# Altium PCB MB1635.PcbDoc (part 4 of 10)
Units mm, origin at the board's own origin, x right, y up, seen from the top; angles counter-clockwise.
Board outline 127 x 97 mm, 6 copper layers (Top Layer, Signal Layer 1, Signal Layer 2, Signal Layer 3, Signal Layer 4, Bottom Layer), stack 1.557 mm thick; 593 components, 478 nets, 2435 pads, 1743 vias.
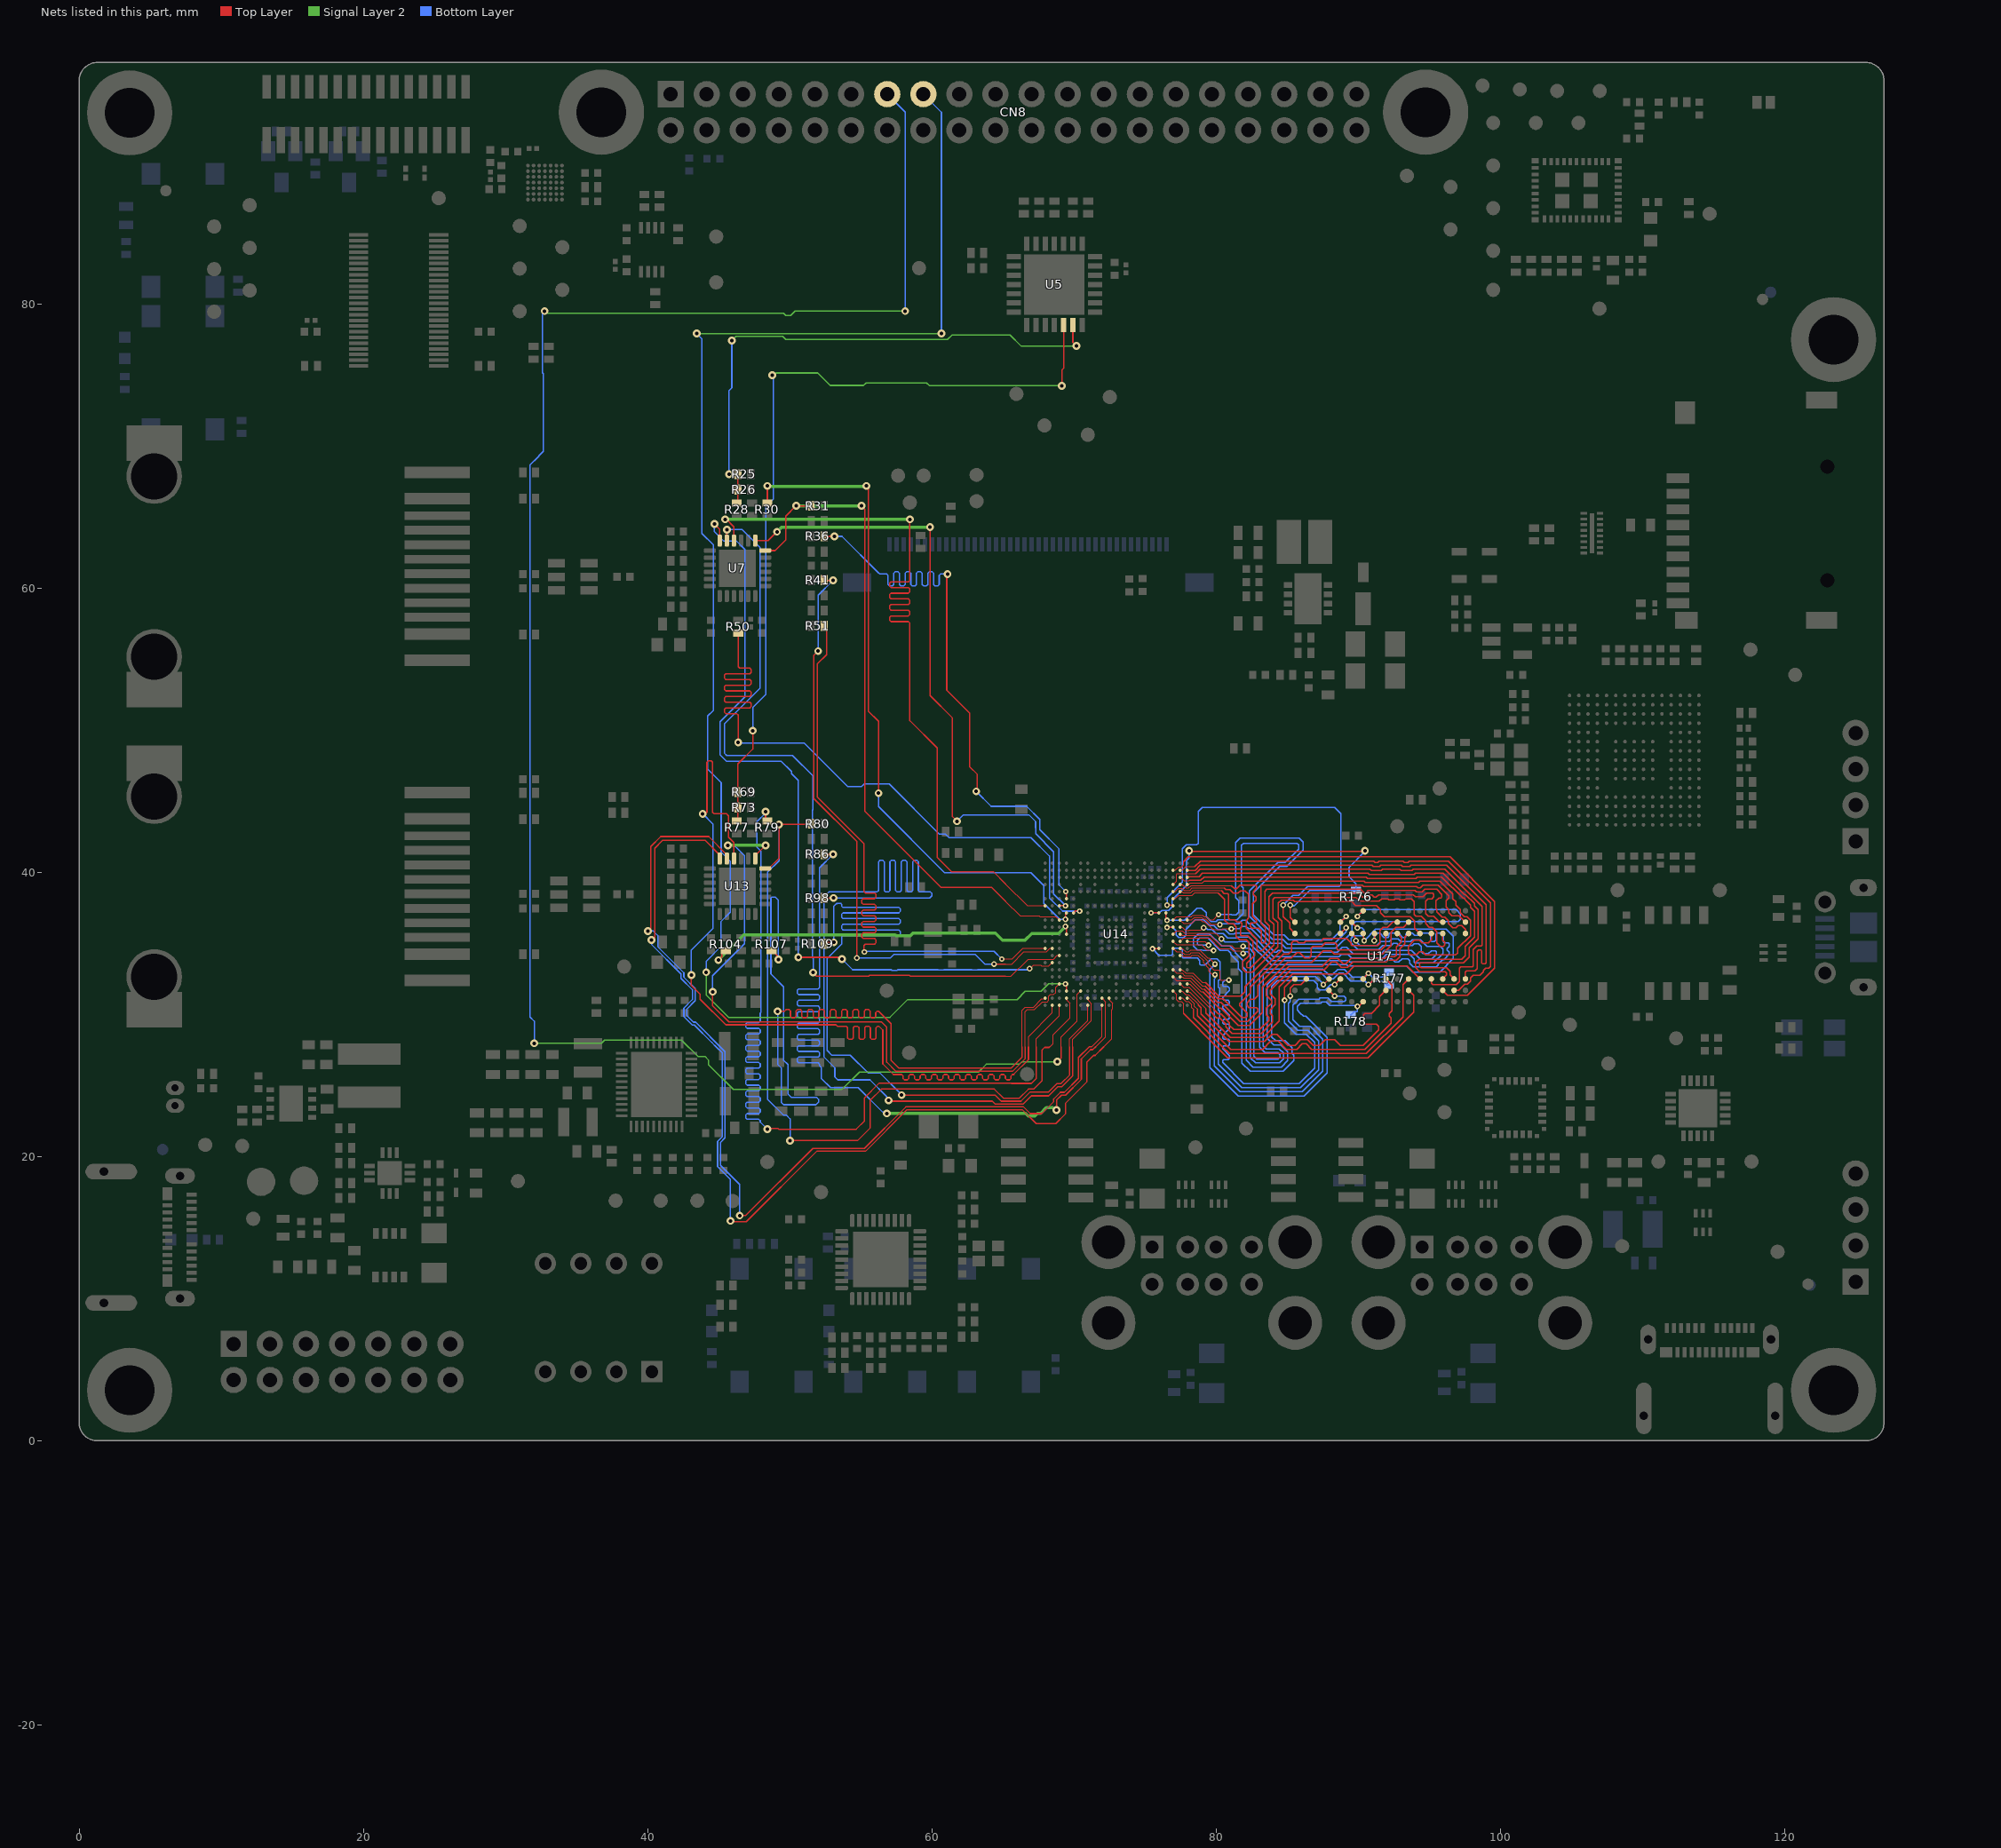
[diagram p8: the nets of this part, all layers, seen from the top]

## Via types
v1: diameter 0.55, hole 0.25, Top Layer to Bottom Layer, 1438 vias
v2: diameter 0.4, hole 0.2, Top Layer to Bottom Layer, 276 vias
v3: diameter 0.26, hole 0.1, Top Layer to Signal Layer 1, tented both sides, 29 vias

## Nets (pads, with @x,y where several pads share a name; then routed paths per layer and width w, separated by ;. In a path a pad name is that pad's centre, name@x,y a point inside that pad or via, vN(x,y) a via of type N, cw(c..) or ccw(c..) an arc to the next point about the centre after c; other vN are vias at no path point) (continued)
DDR_A11: U14.N17 U17.R7 | length 31.2
  Top Layer w0.09: v2(75.525,34.625) 75.538,34.638 75.962,34.638 U14.N17@75.975,34.65 ; v2(85.225,31.3) 85.211,31.314 85.211,31.84 85.475,32.104 85.974,32.104 86.35,32.48 U17.R7@86.35,32.5
  Bottom Layer w0.09: v2(75.525,34.625) 75.978,34.173 76.873,34.173 76.951,34.251 76.951,34.551 77.05,34.65 77.525,34.65 77.625,34.55 77.625,34.05 77.7,33.975 78.675,33.975 78.85,33.8 78.85,33.55 78.925,33.475 79.225,33.475 79.65,33.9 80.063,33.9 80.27,33.693 80.27,32.47 80.171,32.371 80.171,31.93 80.25,31.851 80.25,31.4 80.171,31.321 80.171,30.319 80.257,30.232 80.257,29.793 80.171,29.706 80.171,29.179 80.331,29.019 80.331,28.924 80.171,28.764 80.171,26.496 81.819,24.849 85.953,24.849 87.22,26.115 87.22,28.148 86.478,28.89 85.737,28.89 85.1,29.527 85.1,30.783 85.225,30.908 v2(85.225,31.3)
DDR_A12: U14.M19 U17.N7 | length 31.3
  Top Layer w0.075: U14.M19@76.98,35.145 77.225,34.9 78.962,34.9 79.332,34.53 79.795,34.53 v2(79.825,34.5)
  Top Layer w0.1: v2(87.55,32.1) U17.N7@87.95,32.5
  Bottom Layer w0.09: v2(79.825,34.5) 79.065,34.5 79.01,34.555 78.685,34.555 78.41,34.83 78.41,35.345 78.745,35.68 79.532,35.68 80.244,34.969 ; 80.249,34.974 80.413,34.81 80.963,34.81 81.335,34.438 81.335,34.358 81.865,33.828 81.865,33.34 82.115,33.09 82.115,26.776 82.593,26.299 84.587,26.299 85.04,26.751 85.04,27.399 84.574,27.865 84.055,27.865 83.61,28.31 83.61,32.09 84.185,32.665 87.008,32.665 87.55,32.123 v2(87.55,32.1)
DDR_A13: U14.G19 U17.T3 | length 30.7
  Top Layer w0.09: v2(84.725,37.7) 84.725,36.897 85.175,36.447 85.175,36.065 U17.T3@85.545,35.695
  Top Layer w0.1: v2(76.55,37.7) 76.925,37.7 U14.G19@76.975,37.65
  Bottom Layer w0.09: v2(76.55,37.7) 76.55,38.237 77.625,39.312 77.625,41.675 77.896,41.946 78.639,41.946 78.745,42.052 78.745,43.125 78.745,44.295 79.02,44.57 88.33,44.57 88.775,44.125 88.775,39.125 88.67,39.02 86.453,39.02 85.808,38.375 85.4,38.375 v2(84.725,37.7)
DDR_A14: U14.N19 U17.T7 | length 30.9
  Top Layer w0.075: U14.N19@76.975,34.65 77.225,34.4 77.573,34.4 77.642,34.331 77.693,34.331 77.789,34.234 77.802,34.234 77.866,34.234 78.147,34.234 78.267,34.355 78.786,34.355 79.425,33.716 79.425,33.559 79.839,33.145 80.18,33.145 80.27,33.055 80.27,32.48 80.325,32.425 v2(80.9,32.425)
  Top Layer w0.09: v2(84.825,31) 84.825,31.901 85.424,32.5 U17.T7@85.55,32.5
  Bottom Layer w0.09: v2(80.9,32.425) 80.635,32.425 80.461,32.251 80.461,32.05 80.536,31.975 80.825,31.975 80.955,31.845 80.955,31.695 80.461,31.201 80.461,31.089 80.55,31 80.85,31 80.955,30.895 80.955,30.788 80.848,30.68 80.58,30.68 80.461,30.561 80.461,30.439 80.955,29.945 80.955,29.755 80.875,29.675 80.55,29.675 80.461,29.586 80.461,29.414 80.55,29.325 80.875,29.325 80.955,29.245 80.955,28.995 80.461,28.501 80.461,28.364 80.575,28.25 80.875,28.25 80.955,28.17 80.955,27.88 80.875,27.8 80.536,27.8 80.461,27.725 80.461,27.589 80.95,27.1 80.95,26.925 80.85,26.825 80.525,26.825 80.461,26.761 80.461,26.632 81.955,25.139 85.833,25.139 86.93,26.235 86.93,28.028 86.358,28.6 85.617,28.6 84.81,29.407 84.81,30.985 v2(84.825,31)
DDR_A15: U14.M21 U17.M7 | length 29.8
  Top Layer w0.075: U14.M21@77.975,35.15 78,35.125 79.225,35.125 v2(79.475,34.875)
  Top Layer w0.09: v2(88.35,32.1) U17.M7@88.75,32.5
  Bottom Layer w0.09: v2(79.475,34.875) 78.775,34.875 78.7,34.95 78.7,35.225 78.85,35.375 79.438,35.375 80.293,34.52 80.843,34.52 81.045,34.318 81.045,34.238 81.575,33.708 81.575,33.22 81.825,32.97 81.825,26.58 82.396,26.009 84.707,26.009 85.457,26.759 85.457,27.132 85.33,27.26 85.33,27.656 84.831,28.155 84.175,28.155 83.9,28.43 83.9,31.97 84.305,32.375 86.888,32.375 87.125,32.138 87.125,31.875 87.26,31.74 87.69,31.74 88.05,32.1 v2(88.35,32.1)
DDR_BA0: U14.J19 U17.M2 | length 30.8
  Top Layer w0.075: U14.J19@76.97,36.645 77.175,36.85 77.222,36.897 78.287,36.897 78.29,36.9 78.293,36.9 78.386,36.993 79.059,36.993 79.164,36.889 79.324,36.889 79.532,36.68 79.818,36.68 80.163,37.025 v2(80.175,37.025)
  Top Layer w0.09: U17.M2@88.745,36.495 v2@89.145,36.895
  Bottom Layer w0.09: v2(80.175,37.025) 81.087,37.025 81.107,37.005 81.393,37.005 81.595,37.207 81.595,38.018 81.388,38.225 81.388,42.103 81.685,42.4 85.85,42.4 86.125,42.125 86.125,41.563 84.967,40.405 84.474,40.405 82.64,38.57 82.64,37.006 84.056,35.59 84.796,35.59 85.141,35.245 88.124,35.245 88.735,35.855 88.735,36.485 v2(89.15,36.9)
DDR_BA1: U14.P20 U17.N8 | length 30.3
  Top Layer w0.075: U14.P20@77.475,34.15 77.635,34.15 77.719,34.065 78.217,34.065 78.325,34.174 78.719,34.174 79.113,33.779 79.113,33.63 79.51,33.234 79.51,33.05 79.76,32.8 v2(79.925,32.8)
  Top Layer w0.09: U17.N8@87.95,31.7 v2(88.35,31.3)
  Bottom Layer w0.09: v2(79.925,32.8) 79.925,32.55 79.87,32.495 79.87,26.387 81.699,24.559 86.073,24.559 87.51,25.995 87.51,28.268 86.623,29.155 85.882,29.155 85.405,29.632 85.405,30.678 85.812,31.085 87.25,31.085 87.325,31.16 87.863,31.16 88.113,30.91 89.035,30.91 89.125,31 89.125,31.175 89,31.3 v2(88.35,31.3)
DDR_BA2: U14.H18 U17.M3 | length 31.6
  Top Layer w0.09: U14.H18@76.475,37.15 76.475,36.784 76.55,36.709 v2(76.55,36.625) ; U17.M3@88.745,35.695 v2@89.125,36.075
  Bottom Layer w0.09: v2(76.55,36.625) 77.789,36.625 78.653,37.489 78.986,37.489 79.312,37.163 79.312,36.888 79.65,36.55 80.007,36.55 80.137,36.68 81.478,36.68 81.905,37.107 81.905,38.923 81.775,39.053 81.775,41.9 81.925,42.05 85.7,42.05 85.8,41.95 85.8,41.648 84.847,40.695 84.354,40.695 82.35,38.69 82.35,36.914 83.964,35.3 84.676,35.3 85.026,34.95 88.292,34.95 89.15,35.808 v2(89.15,36.1)
DDR_CASN: U14.L19 U17.K3 | length 30.4
  Top Layer w0.075: U14.L19@76.974,35.65 77.15,35.825 77.221,35.896 77.631,35.896 77.793,35.734 79.966,35.734 v2(80.375,35.325)
  Top Layer w0.09: U17.K3@90.35,35.7 90.387,35.662 90.387,35.237 v2(90.425,35.2)
  Bottom Layer w0.09: v2(80.375,35.325) 80.387,35.325 80.612,35.1 81.537,35.1 81.582,35.145 82.23,35.145 83.875,33.5 89.195,33.5 89.293,33.402 93.413,33.402 93.841,32.974 95.74,32.974 96.7,33.934 96.7,35.513 96.203,36.01 91.235,36.01 v2(90.425,35.2)
DDR_CKE: R178.2 U14.N20 U17.K9 | length 31.8
  Top Layer w0.075: U14.N20@77.47,34.645 77.627,34.645 77.869,34.403 78.077,34.403 78.212,34.538 78.843,34.538 79.396,33.985 79.49,33.985 v2(79.925,33.55)
  Top Layer w0.09: v2(89.95,30.575) 90.025,30.575 U17.K9@90.35,30.9
  Bottom Layer w0.09: v2(79.925,33.55) 79.925,33.525 79.58,33.18 79.58,26.267 81.579,24.269 84.3,24.269 86.193,24.268 87.8,25.875 87.8,28.388 86.318,29.87 86.145,29.87 85.915,30.1 85.912,30.1 85.705,30.307 85.705,30.568 85.932,30.795 87.37,30.795 87.445,30.87 87.743,30.87 87.993,30.62 89.905,30.62 v2(89.95,30.575) 89.95,30.225 89.91,30.185 89.708,30.185 89.498,29.975 R178.2@89.425,29.975
DDR_CLK_N: R177.2 U14.L20 U17.K7 | length 32.9
  Top Layer w0.075: U14.L20@77.496,35.64 77.526,35.64 77.601,35.565 79.611,35.565 80.335,34.841 81.086,34.841 81.269,34.658 81.758,34.658 v2(81.9,34.8)
  Top Layer w0.09: U17.K7@90.35,32.5 90.35,32.525 v2(90.725,32.9)
  Bottom Layer w0.09: v2(81.9,34.8) 81.973,34.8 82.111,34.661 82.339,34.661 82.665,34.335 82.665,27.066 82.883,26.849 84.359,26.849 84.49,26.979 84.49,27.171 84.346,27.315 83.437,27.315 83.06,27.692 83.06,32.924 83.356,33.22 83.36,33.22 ; 83.36,33.21 87.494,33.21 87.929,32.775 88.15,32.775 88.55,33.175 89.035,33.175 89.585,32.625 90.45,32.625 v2(90.725,32.9) 91,32.625 91.725,32.625 92.075,32.975 R177.2@92.175,32.975
DDR_CLK_P: R177.1 U14.M20 U17.J7 | length 33
  Top Layer w0.075: U14.M20@77.475,35.15 77.721,35.396 78.118,35.396 78.144,35.37 79.53,35.37 80.254,34.646 81.005,34.646 81.188,34.463 81.737,34.463 v2(81.9,34.3)
  Top Layer w0.09: v2(90.725,32.1) 90.75,32.1 U17.J7@91.15,32.5
  Bottom Layer w0.09: v2(81.9,34.3) 81.975,34.3 82.076,34.401 82.231,34.401 82.405,34.227 82.405,26.959 82.775,26.589 84.467,26.589 84.75,26.871 84.75,27.279 84.454,27.575 83.544,27.575 83.32,27.799 83.32,32.816 83.453,32.95 87.38,32.95 87.386,32.95 87.821,32.515 88.258,32.515 88.658,32.915 88.927,32.915 89.477,32.365 90.46,32.365 v2(90.725,32.1) ; R177.1@92.175,32.075 92.017,32.075 91.727,32.365 91.015,32.365 v2@90.75,32.1 ; v2(90.725,32.1) v2@90.75,32.1 ; v2(90.725,32.1) v2@90.75,32.1
DDR_CSN: U14.J20 U17.L2 | length 30.3
  Top Layer w0.075: U14.J20@77.47,36.645 77.715,36.4 78.274,36.4 78.527,36.653 78.918,36.653 79.023,36.549 79.183,36.549 79.706,36.026 ; 79.706,36.02 79.815,36.02 79.855,35.98 80.413,35.98 80.458,36.025 v2(81.075,36.025)
  Top Layer w0.09: U17.L2@89.545,36.495 v2(89.945,36.095)
  Bottom Layer w0.09: v2(81.075,36.025) 81.645,36.025 81.82,36.2 82.1,36.2 82.275,36.025 82.474,36.025 84.129,34.37 84.245,34.37 84.378,34.503 84.653,34.503 84.786,34.37 88.532,34.37 88.887,34.725 89.2,34.725 89.651,34.274 91.617,34.274 91.848,34.505 93.745,34.505 94.33,33.92 95.177,33.92 95.5,34.243 95.5,34.4 95.425,34.475 95.15,34.475 94.95,34.275 94.55,34.275 94.425,34.4 94.425,34.802 94.252,34.975 93.935,34.975 93.81,34.85 92.89,34.85 92.732,35.007 92.478,35.007 92.321,34.85 91.711,34.85 91.425,34.565 89.96,34.565 89.5,35.025 89.5,35.338 89.702,35.54 90.24,35.54 90.4,35.7 90.4,35.95 90.255,36.095 v2(89.945,36.095)
DDR_DQ0: U14.B21 U17.A7 | length 30.9
  Top Layer w0.09: U14.B21@77.97,40.145 78.52,40.145 78.89,40.515 81.275,40.515 90.977,40.515 91.073,40.42 91.505,40.42 91.6,40.515 93.043,40.515 93.138,40.42 93.625,40.42 93.72,40.515 96.222,40.515 99.015,37.721 99.015,33.64 98.94,33.565 98.753,33.565 98.7,33.617 98.7,34.484 98.647,34.536 98.465,34.536 98.375,34.446 98.375,33.219 98.215,33.06 97.635,33.06 97.539,32.964 97.539,32.501 U17.A7@97.545,32.495
DDR_DQ1: U14.B20 U17.B8 | length 31.4
  Top Layer w0.075: U14.B20@77.475,40.15 77.485,40.16 77.636,40.16 77.876,40.4 78.513,40.4
  Top Layer w0.09: 78.513,40.4 78.918,40.805 91.098,40.805 91.193,40.71 91.377,40.71 91.472,40.805 93.163,40.805 93.258,40.71 93.505,40.71 93.6,40.805 96.342,40.805 99.305,37.842 99.305,33.39 99.19,33.275 98.975,33.275 98.8,33.1 98.8,33 98.57,32.77 98.085,32.77 97.895,32.58 97.895,32.351 97.689,32.145 97.495,32.145 97.05,31.7 U17.B8@96.75,31.7
DDR_DQ2: U14.D19 U17.D7 | length 32.7
  Top Layer w0.075: U14.D19@76.97,39.145 77.221,39.396 77.221,39.856 77.265,39.9 78.555,39.9
  Top Layer w0.09: 78.555,39.9 78.88,40.225 81.275,40.225 90.829,40.225 90.924,40.13 91.625,40.13 91.72,40.225 92.923,40.225 93.018,40.13 93.775,40.13 93.87,40.225 96.101,40.225 98.725,37.601 98.725,34.9 98.652,34.826 98.345,34.826 98.085,34.566 98.085,33.404 98.032,33.351 97.217,33.351 97.14,33.274 97.14,32.323 96.917,32.1 95.254,32.1 95.15,32.204 U17.D7@95.15,32.5
DDR_DQ3: U14.E19 U17.A3 | length 32.6
  Top Layer w0.075: U14.E19@76.996,38.671 77.15,38.671 77.228,38.75 77.228,38.752 77.373,38.897 77.603,38.897 77.765,38.735 77.805,38.735 78.147,38.735 78.312,38.9 80.575,38.9
  Top Layer w0.09: 80.575,38.9 80.7,38.775 80.98,38.775 81.23,38.525 81.54,38.525 81.717,38.702 82.036,38.702 82.275,38.463 82.275,36.775 82.115,36.615 82.115,36.07 82.888,35.298 82.888,34.598 83.015,34.47 83.225,34.47 83.759,35.005 83.759,36.223 83.435,36.547 83.435,38.677 83.572,38.815 90.165,38.815 90.43,38.55 90.522,38.55 90.692,38.72 93.99,38.72 94.085,38.625 94.49,38.625 94.68,38.815 95.517,38.815 95.885,38.447 95.885,38.247 95.832,38.195 95.675,38.195 95.48,37.999 95.48,37.45 95.525,37.404 95.525,37.219 95.9,36.845 96.09,36.845 96.345,36.59 96.345,36.4 96.647,36.098 96.873,36.098 97.025,36.25 97.291,36.25 97.55,35.991 U17.A3@97.55,35.7
DDR_DQ4: U14.B19 U17.C8 | length 33.7
  Top Layer w0.075: U14.B19@76.975,40.15 76.985,40.16 77.136,40.16 77.373,40.397 77.589,40.397 77.725,40.532 77.725,40.773
  Top Layer w0.09: 77.725,40.773 78.047,41.095 79.4,41.095 96.462,41.095 99.595,37.962 99.595,33.254 97.694,31.354 96.296,31.354 U17.C8@95.95,31.7
DDR_DQ5: U14.D20 U17.A2 | length 32
  Top Layer w0.075: U14.D20@77.484,39.131 77.637,39.131 77.865,38.904 78.077,38.904 78.248,39.075 80.5,39.075 80.502,39.077 80.648,39.077 80.65,39.075 81.075,39.075
  Top Layer w0.09: 81.075,39.075 81.3,38.85 81.455,38.85 81.705,39.1 82.775,39.1 82.85,39.025 82.85,38.875 82.617,38.642 82.617,38.433 82.803,38.247 82.803,38.028 82.565,37.79 82.565,36.91 82.85,36.625 82.85,36.5 82.795,36.445 82.47,36.445 82.405,36.38 82.405,36.19 82.525,36.07 83.005,36.07 83.178,35.897 83.178,35.078 83.23,35.025 83.37,35.025 83.469,35.125 83.469,36.102 83.145,36.427 83.145,39.045 83.205,39.105 90.285,39.105 90.38,39.01 94.11,39.01 94.205,38.915 94.37,38.915 94.56,39.105 95.638,39.105 96.379,38.363 96.379,38.203 96.175,37.999 96.175,37.56 96.387,37.348 96.387,37.172 96.604,36.955 97.085,36.955 U17.A2@97.545,36.495
DDR_DQ6: U14.E20 U17.C2 | length 32
  Top Layer w0.075: U14.E20@77.492,38.623 77.637,38.623 77.695,38.566 77.875,38.566 ; 77.875,38.566 78.217,38.566 78.227,38.575 78.383,38.731 80.364,38.731 80.364,38.729 80.364,38.723
  Top Layer w0.09: 80.377,38.723 80.58,38.52 80.825,38.52 80.885,38.46 80.885,36.765 80.975,36.675 81.325,36.675 81.477,36.523 81.727,36.523 81.825,36.425 81.825,36.2 81.71,36.085 81.71,35.615 81.785,35.54 82.235,35.54 82.598,35.177 82.598,34.477 82.725,34.35 82.725,34.155 82.165,33.595 82.165,33.329 82.218,33.276 82.441,33.276 84.049,34.884 84.049,36.343 83.725,36.667 83.725,38.29 83.96,38.525 90.045,38.525 90.31,38.26 90.642,38.26 90.812,38.43 90.957,38.43 91.127,38.26 91.266,38.26 91.436,38.43 92.208,38.43 93.87,38.43 94.025,38.275 94.55,38.275 94.8,38.525 95.25,38.525 95.325,38.45 95.325,38.275 95.195,38.145 94.902,38.145 94.75,37.993 94.75,37.1 94.95,36.9 95.2,36.9 ; 95.2,36.9 95.325,36.9 95.685,36.54 95.91,36.54 U17.C2@95.95,36.5
DDR_DQ7: U14.F19 U17.C3 | length 32.8
  Top Layer w0.075: U14.F19@76.989,38.164 77.138,38.164 77.372,38.397 78.324,38.397 78.49,38.562 80.143,38.562 80.143,38.559 80.149,38.559 80.153,38.554
  Top Layer w0.09: 80.153,38.554 80.158,38.554 80.595,38.118 80.595,36.645 80.865,36.375 81.215,36.375 81.42,36.17 81.42,35.48 81.65,35.25 82.115,35.25 82.308,35.057 82.308,34.148 81.875,33.715 81.875,33.199 82.088,32.986 82.561,32.986 84.339,34.764 84.339,36.463 84.015,36.787 84.015,38.115 84.135,38.235 89.875,38.235 ; 89.9,38.21 90.14,37.97 91.475,37.97 91.645,38.14 92.088,38.14 92.171,38.056 92.518,38.056 92.602,38.14 92.888,38.14 92.953,38.075 93.266,38.075 93.331,38.14 93.75,38.14 93.947,37.943 93.947,37.028 94.075,36.9 94.45,36.9 94.745,36.605 94.745,36.4 95,36.145 95.215,36.145 95.525,35.835 95.525,35.046 95.771,34.8 96,34.8 96.1,34.9 96.1,35.08 95.95,35.23 U17.C3@95.95,35.7
DDR_DQ8: U14.T20 U17.E3 | length 24.3
  Top Layer w0.075: U14.T20@77.48,33.135 77.634,33.135 77.865,32.903 78.185,32.903 78.375,32.903 79.034,32.244 79.256,32.244
  Top Layer w0.09: 79.256,32.244 80.2,31.3 81.735,31.3 82.025,31.59 82.025,31.95 84.629,34.554 84.629,36.583 84.38,36.832 84.38,37.843 84.582,38.045 85.43,38.045 85.53,37.945 89.564,37.945 89.829,37.68 91.287,37.68 91.57,37.396 91.57,37.175 91.85,36.895 93.65,36.895 93.965,36.58 93.965,36.085 U17.E3@94.345,35.705
DDR_DQ9: U14.U20 U17.H3 | length 22.2
  Top Layer w0.075: U14.U20@77.47,32.645 77.643,32.645 77.723,32.565 78.235,32.565 79,31.8 79.15,31.8
  Top Layer w0.09: 79.15,31.8 80.088,30.863 80.338,30.863 81.69,29.51 82.22,29.51 82.95,30.24 82.95,30.375 82.85,30.475 82.325,30.475 82.175,30.625 82.175,30.825 82.413,31.063 82.688,31.063 82.95,31.325 82.95,32.04 84.88,33.97 85.295,33.97 85.675,34.35 85.875,34.35 86.255,33.97 86.55,33.97 86.7,34.12 86.7,34.675 86.81,34.785 87.435,34.785 87.687,35.037 88.373,35.037 88.5,34.91 88.5,34.625 88.575,34.55 89.592,34.55 91.599,34.55 91.945,34.896 U17.H3@91.945,35.695
DDR_DQ10: U14.T19 U17.G2 | length 22.9
  Top Layer w0.075: U14.T19@76.975,33.15 77.225,32.9 77.628,32.9 77.794,32.734 78.305,32.734 79.039,32 79.225,32
  Top Layer w0.09: 79.225,32 80.116,31.109 80.516,31.109 81.825,29.8 82.1,29.8 82.175,29.875 82.175,30.1 81.65,30.625 81.65,30.765 82.4,31.515 82.4,31.9 84.76,34.26 85.11,34.26 85.3,34.45 85.3,35.04 85.439,35.178 85.675,35.178 85.828,35.025 86.175,35.025 86.328,35.178 87.419,35.178 87.578,35.337 89.188,35.337 89.5,35.025 89.5,34.9 89.56,34.84 89.712,34.84 91.278,34.84 91.39,34.84 91.548,34.998 91.548,35.923 91.75,36.125 92.075,36.125 92.445,36.495 U17.G2@92.745,36.495
DDR_DQ11: U14.W20 U17.H8 | length 21.9
  Top Layer w0.075: U14.W20@77.48,31.635 77.634,31.635 77.872,31.396 78.079,31.396 78.75,30.725
  Top Layer w0.09: 78.75,30.725 78.75,30.675 78.95,30.475 78.95,30.045 80.895,28.1 83.424,28.1 83.932,28.608 84.297,28.608 85.075,27.83 85.555,27.83 85.95,28.225 86.455,28.225 86.85,27.83 87.28,27.83 87.675,28.225 88.355,28.225 88.75,27.83 90.339,27.83 91.425,28.916 91.425,29.168 91.268,29.325 90.5,29.325 90.375,29.45 90.375,29.967 90.483,30.075 90.925,30.075 91.5,30.65 91.5,31.25 U17.H8@91.95,31.7 U17.H8@91.925,31.7
DDR_DQ12: U14.W19 U17.F8 | length 22.5
  Top Layer w0.075: U14.W19@76.975,31.65 77.225,31.4 77.225,31.026 77.348,30.903 77.569,30.903 77.721,30.752 77.721,30.548 77.706,30.533 77.706,30.059
  Top Layer w0.09: 77.706,30.059 80.04,27.725 80.805,26.96 90.699,26.96 93.895,30.156 93.895,31.345 U17.F8@93.545,31.695
DDR_DQ13: U14.U19 U17.F2 | length 22.8
  Top Layer w0.075: U14.U19@76.975,32.65 77.229,32.396 78.154,32.396 78.95,31.6 79.075,31.6
  Top Layer w0.09: 79.075,31.6 80.218,30.457 80.332,30.457 81.57,29.22 82.34,29.22 83.24,30.12 83.24,31.9 85.02,33.68 86.727,33.68 87.523,34.475 88.1,34.475 88.315,34.26 89.675,34.26 91.325,34.26 91.719,34.26 92.32,34.861 92.32,35.795 92.65,36.125 93.175,36.125 U17.F2@93.545,36.495
DDR_DQ14: U14.Y21 U17.H7 | length 21.2
  Top Layer w0.075: U14.Y21@77.992,31.123 78.101,31.123 78.475,30.749 78.475,30.575 78.675,30.375
  Top Layer w0.09: 78.675,30.375 78.675,29.91 80.86,27.725 81.046,27.54 83.274,27.54 83.859,28.125 84.37,28.125 84.955,27.54 85.675,27.54 86.07,27.935 86.335,27.935 86.73,27.54 90.459,27.54 92.3,29.381 92.3,29.775 92.175,29.9 92.175,30.066 92.37,30.261 92.37,32.07 U17.H7@91.945,32.495
DDR_DQ15: U14.Y20 U17.F7 | length 21.7
  Top Layer w0.075: U14.Y20@77.474,31.15 77.625,31.15 77.872,30.903 78.072,30.903 78.288,30.688 78.288,30.492 78.4,30.379
  Top Layer w0.09: 78.414,30.365 78.414,30.085 78.4,30.071 78.4,29.775 80.45,27.725 80.925,27.25 90.579,27.25 93.15,29.821 93.15,32.1 U17.F7@93.55,32.5
DDR_DQM0: U14.D21 U17.D3 | length 31.1
  Top Layer w0.075: U14.D21@77.956,39.143 78.074,39.143 78.201,39.27 79.045,39.27 79.17,39.395
  Top Layer w0.09: 79.17,39.395 81.275,39.395 90.405,39.395 90.5,39.3 94.253,39.3 94.348,39.395 95.758,39.395 96.669,38.484 96.669,38.144 96.87,37.943 96.87,37.7 97.195,37.375 97.195,37.15 97.463,36.882 97.653,36.882 97.895,36.64 97.895,35.55 96.995,34.65 96.995,34.32 96.86,34.185 94.765,34.185 94.525,34.425 94.325,34.425 94.085,34.185 93.665,34.185 93.525,34.325 93.525,34.8 93.95,35.225 94.3,35.225 94.495,35.03 94.93,35.03 95.145,35.245 U17.D3@95.145,35.695
DDR_DQM1: U14.W21 U17.E7 | length 21.7
  Top Layer w0.075: U14.W21@78.013,31.645 78.016,31.645 78.096,31.565 78.159,31.565 79.295,30.43
  Top Layer w0.09: 79.295,30.43 79.295,30.111 81.015,28.39 83.304,28.39 84.45,29.536 84.45,31.936 85.363,32.85 89.175,32.85 89.73,33.405 93.096,33.405 93.111,33.42 93.439,33.42 94.35,32.508 U17.E7@94.35,32.5
DDR_DQS0_N: U14.C21 U17.B7 | length 32.3
  Top Layer w0.09: U14.C21@77.975,39.65 78.032,39.707 78.814,39.707 79.047,39.94 81.275,39.94 90.681,39.94 90.776,39.845 93.949,39.845 94.044,39.94 95.983,39.94 97.473,38.45 97.544,38.45 98.181,37.813 98.181,37.634 98.44,37.375 98.44,35.324 97.805,34.689 97.805,34.039 97.405,33.64 94.377,33.64 94.3,33.563 94.3,33.417 94.433,33.285 96.233,33.285 96.485,33.032 96.485,32.787 96.75,32.522 U17.B7@96.75,32.5
DDR_DQS0_P: U14.C20 U17.C7 | length 32.4
  Top Layer w0.075: U14.C20@77.496,39.65 77.746,39.4 78.093,39.4 78.139,39.447
  Top Layer w0.09: U14.C20@77.475,39.65 U14.C20@77.496,39.65 ; 78.139,39.447 78.922,39.447 79.155,39.68 81.275,39.68 90.573,39.68 90.668,39.585 94.056,39.585 94.151,39.68 95.876,39.68 97.366,38.19 97.436,38.19 97.665,37.961 97.921,37.705 97.921,37.526 98.18,37.267 98.18,35.432 97.545,34.797 97.545,34.147 97.298,33.9 94.269,33.9 94.04,33.671 94.04,33.31 94.325,33.025 96.125,33.025 96.225,32.925 96.225,32.8 95.95,32.525 U17.C7@95.95,32.5
DDR_DQS1_N: U14.V21 U17.G3 | length 22.3
  Top Layer w0.075: U14.V21@77.963,32.161 U14.V21@77.974,32.15 78.003,32.12 78.15,32.12 79.845,30.425
  Top Layer w0.09: 79.845,30.425 79.845,30.339 80.154,30.029 80.351,30.029 80.95,29.43 80.95,29.233 81.243,28.94 83.076,28.94 83.715,29.579 83.715,29.794 83.54,29.969 83.54,30.433 83.9,30.793 83.9,30.992 83.54,31.352 83.54,31.79 85.14,33.39 87.476,33.39 88.031,33.945 88.559,33.945 88.936,33.568 89.129,33.568 89.506,33.945 91.87,33.945 92,34.075 92.575,34.075 92.675,34.175 92.675,34.75 93.025,35.1 93.025,35.425 U17.G3@92.75,35.7
DDR_DQS1_P: U14.V20 U17.F3 | length 23.4
  Top Layer w0.075: U14.V20@77.474,32.15 77.725,31.9 78.094,31.9 79.585,30.409
  Top Layer w0.09: 79.585,30.409 79.585,30.231 80.046,29.769 80.243,29.769 80.69,29.322 80.69,29.126 81.136,28.68 83.184,28.68 83.975,29.471 83.975,29.902 83.8,30.077 83.8,30.325 84.16,30.685 84.16,31.1 83.8,31.46 83.8,31.682 85.247,33.13 87.584,33.13 88.139,33.685 88.451,33.685 88.828,33.308 89.237,33.308 89.614,33.685 91.978,33.685 92.108,33.815 92.683,33.815 92.935,34.067 92.935,34.642 93.285,34.992 93.285,35.435 U17.F3@93.55,35.7
DDR_ODT: U14.J21 U17.K1 | length 30.1
  Top Layer w0.075: U14.J21@77.975,36.65 78.283,36.65 78.456,36.823 78.988,36.823 79.093,36.719 79.253,36.719 79.627,36.345 v2@80.27,36.345
  Top Layer w0.09: v2@89.945,36.895 v2(89.95,36.9) U17.K1@90.345,37.295
  Bottom Layer w0.09: v2(80.27,36.325) 80.329,36.384 80.472,36.384 80.478,36.39 81.6,36.39 81.835,36.625 82.09,36.625 82.325,36.39 82.492,36.39 83.886,34.997 84.569,34.997 84.906,34.66 88.412,34.66 89.558,35.806 89.558,36.275 89.808,36.525 97.025,36.525 97.2,36.7 97.2,37.075 96.9,37.375 90.425,37.375 v2(89.95,36.9)
DDR_RASN: U14.K20 U17.J3 | length 30.7
  Top Layer w0.075: U14.K20@77.47,36.145 77.481,36.134 77.633,36.134 77.861,35.905 77.87,35.905 77.872,35.903 78.076,35.903 78.078,35.905 78.084,35.905 78.119,35.941 78.928,35.941 79.087,36.1 v2(79.125,36.1)
  Top Layer w0.09: v2@91.145,35.195 U17.J3@91.145,35.695
  Bottom Layer w0.09: v2(79.125,36.1) 79.184,36.041 79.339,36.041 79.41,35.97 79.727,35.97 80.007,35.69 80.512,35.69 80.812,35.39 81.417,35.39 81.462,35.435 82.315,35.435 83.96,33.79 89.315,33.79 89.411,33.694 91.857,33.694 92.089,33.925 92.35,33.925 92.583,33.692 92.85,33.692 93.083,33.925 93.505,33.925 93.635,33.795 93.635,33.59 93.885,33.34 95.505,33.34 95.632,33.468 95.632,33.555 95.932,33.855 96.02,33.855 96.41,34.245 96.41,34.39 96.25,34.55 96.25,34.625 96.41,34.785 96.41,34.97 96.35,35.03 96.07,35.03 96,35.1 96,35.65 95.93,35.72 95.545,35.72 95.462,35.637 95.462,35.237 95.35,35.125 95.15,35.125 95.095,35.18 95.095,35.663 95.038,35.72 94.37,35.72 94.225,35.575 93.97,35.575 93.825,35.72 93.436,35.72 93.352,35.636 93.352,35.485 93.297,35.43 93.13,35.43 92.84,35.72 92.225,35.72 92.15,35.645 92.15,35.5 92.08,35.43 91.82,35.43 91.53,35.72 91.355,35.72 91.125,35.49 v2(91.125,35.2)
DDR_RESETN: R176.2 U14.H17 U17.T2 | length 29
  Top Layer w0.09: v2(75.425,37.15) U14.H17@75.975,37.15 ; v1(78.1,41.525) 78.146,41.479 81.275,41.479 90.475,41.479 v1(90.475,41.525) ; v2(85.225,37.7) 85.211,37.686 85.211,36.829 U17.T2@85.545,36.495
  Bottom Layer w0.09: v2(75.425,37.15) 76.01,37.15 76.19,37.33 76.668,37.33 76.895,37.557 76.895,38.062 77.915,39.082 77.915,40.825 78.1,41.01 v1(78.1,41.525)
  Bottom Layer w0.1: v2(85.225,37.7) 85.225,37.694 85.178,37.647 85.497,37.647 86.575,38.725 R176.2@89.85,38.725 89.85,39.2 89.361,39.689 89.361,40.361 v1@90.475,41.475
DDR_WEN: U14.K19 U17.L3 | length 30.9
  Top Layer w0.09: v2@76.563,36.145 76.57,36.145 U14.K19@76.97,36.145 ; U17.L3@89.55,35.7 89.55,35.69 89.798,35.442 89.798,35.242 v2(89.845,35.195)
  Top Layer w0.1: v2(76.55,36.125) v2@76.57,36.145 ; U14.K19@76.97,36.145 U14.K19@76.975,36.15
  Bottom Layer w0.09: v2(76.55,36.125) 76.95,36.125 77.2,35.875 77.2,35.6 77.375,35.425 77.723,35.425 77.875,35.577 77.875,35.988 78.537,36.65 79.14,36.65 79.53,36.26 79.847,36.26 80.127,35.98 80.632,35.98 80.932,35.68 81.297,35.68 81.342,35.725 82.399,35.725 84.045,34.08 88.652,34.08 88.799,34.226 89.288,34.226 89.531,33.984 91.737,33.984 91.968,34.215 93.625,34.215 93.925,33.915 93.925,33.71 94.005,33.63 95.297,33.63 95.96,34.293 95.96,34.6 95.77,34.79 94.847,34.79 94.372,35.265 93.815,35.265 93.69,35.14 93.01,35.14 92.825,35.325 92.385,35.325 92.201,35.14 91.59,35.14 91.305,34.855 90.12,34.855 89.845,35.13 v2(89.845,35.195)
DFSDM1_CKOUT: CN8.13 U14.W6 | length 138.6
  Top Layer w0.075: 69.1,27.725 69.1,28.419 70.228,29.547 70.228,31.403 U14.W6@70.475,31.65
  Top Layer w0.1: v1(68.825,26.675) 68.85,26.675 69.1,26.925 69.1,27.725
  Signal Layer 2 w0.09: v1(32.752,79.504) 32.896,79.359 49.578,79.359 49.728,79.209 50.076,79.209 50.368,79.5 v1(58.125,79.5)
  Signal Layer 2 w0.1: v1(32.025,27.975) 36.756,27.975 36.981,28.2 42.383,28.2 43.532,27.051 44.028,27.051 44.277,26.802 44.277,26.484 46.036,24.725 53.675,24.725 54.905,25.955 63.28,25.955 63.825,26.5 66.151,26.5 66.326,26.675 v1(68.825,26.675)
  Bottom Layer w0.09: 32.025,68.975 32.675,69.625 32.675,75.106 32.605,75.176 32.605,79.43 32.679,79.504 v1(32.752,79.504) ; CN8.13@56.86,94.77 58.125,93.505 v1(58.125,79.5)
  Bottom Layer w0.1: v1(32.025,27.975) 32.025,29.525 31.725,29.825 31.725,68.675 32.025,68.975
DFSDM1_DATIN3: CN8.15 U14.W4 | length 110.5
  Top Layer w0.1: v2@69.45,32.1 69.463,32.088 69.463,31.662 U14.W4@69.475,31.65
  Signal Layer 2 w0.09: 65.175,31.05 66,31.05 66.575,31.625 67.7,31.625 68.225,32.15 v2(69.4,32.15)
  Signal Layer 2 w0.1: v1(43.45,77.925) v1(60.675,77.925) ; v1(44.125,32.975) 44.125,31.375 45.7,29.8 57.05,29.8 58.3,31.05 65.175,31.05
  Bottom Layer w0.1: v1(43.45,77.925) 43.825,77.55 43.825,63.85 44.625,63.05 44.625,51.4 44.225,51 44.225,47.267 45.175,46.317 45.175,41.425 45.825,40.775 45.825,37.2 45.15,36.525 45.15,34.775 44.125,33.75 v1(44.125,32.975) ; CN8.15@59.4,94.77 60.675,93.495 v1(60.675,77.925)
ETH1_CLK: R107.1 U14.Y1 | length 64.9
  Top Layer w0.075: 66.35,27.725 66.35,30.3 66.575,30.525 67.167,30.525 67.736,31.094 67.877,31.094 67.915,31.133 U14.Y1@67.915,31.15
  Top Layer w0.1: R107.1@48.725,34.5 48.775,34.5 49.2,34.075 v1(49.2,33.875) ; v1(49.15,30.225) 49.25,30.225 49.625,30.225 49.65,30.25 49.75,30.35 49.95,30.35 50.05,30.25 50.05,30.225 50.05,29.875 50.15,29.775 50.35,29.775 50.45,29.875 50.45,30.225 50.45,30.25 50.55,30.35 50.75,30.35 50.85,30.25 50.85,30.225 50.85,29.875 50.95,29.775 51.15,29.775 51.25,29.875 51.25,30.225 51.25,30.25 51.35,30.35 51.55,30.35 51.65,30.25 51.65,30.225 51.65,29.875 51.75,29.775 51.95,29.775 52.05,29.875 52.05,30.225 52.05,30.25 52.15,30.35 52.35,30.35 52.45,30.25 52.45,30.225 52.45,29.875 52.55,29.775 52.75,29.775 52.85,29.875 52.85,30.225 52.85,30.25 52.95,30.35 53.15,30.35 53.25,30.25 53.25,30.225 53.25,29.875 53.35,29.775 53.55,29.775 53.65,29.875 53.65,30.225 53.65,30.25 53.75,30.35 53.95,30.35 54.05,30.25 54.05,30.225 54.05,29.875 54.15,29.775 54.35,29.775 54.45,29.875 54.45,30.225 54.45,30.25 54.55,30.35 54.75,30.35 54.85,30.25 54.85,30.225 54.85,29.875 54.95,29.775 55.15,29.775 55.25,29.875 55.25,30.225 55.25,30.25 55.35,30.35 55.55,30.35 55.65,30.25 55.65,30.225 55.65,29.875 55.75,29.775 55.95,29.775 56.05,29.875 56.05,30.125 56.15,30.225 56.25,30.225 57.125,29.35 57.125,26.775 57.675,26.225 65.575,26.225 66.35,27 66.35,27.725
  Bottom Layer w0.1: v1(49.15,30.225) 49.15,26.5 49.4,26.25 49.4,23.825 49.575,23.65 51.85,23.65 52.025,23.825 52.025,24.025 51.875,24.175 50.1,24.175 49.875,24.4 49.875,26.475 49.575,26.775 49.575,31.955 48.675,32.855 48.675,38.191 48.734,38.25 49,38.25 49.2,38.05 v1(49.2,33.875)
ETH1_CRS_DV: R86.1 U14.Y9 | length 64.9
  Top Layer w0.075: 71.526,27.725 72.225,28.424 72.225,30.9 U14.Y9@71.975,31.15
  Top Layer w0.1: R86.1@52.425,41.275 v1(53.05,41.275) ; v1(68.775,23.275) 68.775,23.974 69.127,24.326 69.411,24.326 70.52,25.435 70.52,26.87 71.172,27.522 71.324,27.522 71.526,27.725
  Signal Layer 2 w0.219: v1(56.835,23.035) 56.85,23.05 66.591,23.05 66.782,22.859 67.244,22.859 67.435,23.05 67.65,23.05 68.05,23.45 68.51,23.45 68.685,23.275 v1(68.775,23.275)
  Bottom Layer w0.1: v1(53.05,41.275) 52.1,40.325 52.1,32.025 52.1,31.9 52,31.8 50.625,31.8 50.525,31.7 50.525,31.5 50.625,31.4 52,31.4 52.1,31.3 52.1,31.1 52,31 50.625,31 50.525,30.9 50.525,30.7 50.625,30.6 52,30.6 52.1,30.5 52.1,30.3 52,30.2 50.625,30.2 50.525,30.1 50.525,29.9 50.625,29.8 52,29.8 52.1,29.7 52.1,29.5 52,29.4 50.625,29.4 50.525,29.3 50.525,29.1 50.625,29 52,29 52.1,28.9 52.1,28.7 52,28.6 50.625,28.6 50.525,28.5 50.525,28.3 50.625,28.2 52,28.2 52.1,28.1 52.1,27.9 52,27.8 50.625,27.8 50.525,27.7 50.525,27.5 50.625,27.4 52,27.4 52.1,27.3 52.1,27.1 52,27 50.625,27 50.525,26.9 50.525,26.7 50.625,26.6 52,26.6 52.1,26.5 52.1,26.4 52.225,26.275 52.225,25.5 52.875,24.85 54.825,24.85 56.554,23.121 56.749,23.121 v1(56.835,23.035)
ETH1_MDC: U13.13 U14.V3 | length 49.4
  Top Layer w0.075: 66.575,27.725 66.575,30.2 66.725,30.35 67.231,30.35 67.781,30.9 68.125,30.9 68.225,31 68.225,31.275 68.35,31.4 68.573,31.4 68.725,31.552 68.725,31.9 U14.V3@68.975,32.15
  Top Layer w0.1: v1(44.575,31.6) 44.575,30.625 45.725,29.475 56.45,29.475 56.825,29.1 56.825,26.65 57.475,26 65.675,26 66.575,26.9 66.575,27.725 ; U13.13@47.575,40.975 47.575,41.175 v1(48.3,41.9)
  Signal Layer 2 w0.219: v1(45.65,41.9) v1(48.3,41.9)
  Bottom Layer w0.1: v1(44.575,31.6) 44.575,32.725 46.825,34.975 46.825,41.175 46.1,41.9 v1(45.65,41.9)
ETH1_MDINT: R104.1 U14.L4 | length 27.4
  Top Layer w0.09: U14.L4@69.475,35.65 v2@69.475,36.075
  Top Layer w0.1: v1(44.975,33.825) 45.225,34.075 45.225,34.5 R104.1@45.5,34.5
  Signal Layer 2 w0.219: v1(44.975,33.825) 46.75,35.6 57.425,35.6 57.5,35.525 58.475,35.525 58.675,35.725 64.475,35.725 64.975,35.225 65.175,35.225 66.55,35.225 67.025,35.7 68.9,35.7 v2(69.4,36.2)
ETH1_MDIO: R80.1 U13.12 U14.Y4 | length 57.4
  Top Layer w0.075: 68.3,27.725 68.525,27.95 68.525,28.561 69.721,29.757 69.721,30.779 69.498,31.002 69.498,31.127 U14.Y4@69.475,31.15
  Top Layer w0.1: U13.12@48.275,40.275 48.525,40.275 49.25,41 v1(49.25,43.375) 51.475,43.375 R80.1@51.525,43.425 ; v1(50.025,21.125) 54.775,21.125 55.65,22 55.65,23.95 56.45,24.75 64.4,24.75 65.05,24.1 66.15,24.1 66.8,24.75 67.166,24.75 67.75,25.334 67.75,27.5 67.931,27.681 68.256,27.681 68.3,27.725
  Bottom Layer w0.1: v1(49.25,43.375) 49.25,40.825 48.45,40.025 48.45,24.025 49.549,22.926 49.753,22.926 50.025,22.654 v1(50.025,21.125)
ETH1_NRST: R69.1 R73.1 R77.1 U5.26 | length 57.8
  Top Layer w0.1: R77.1@46.275,43.625 46.35,43.7 R73.1@46.35,44.575 R69.1@46.35,45.65 46.35,47.625 47.4,48.675 v1(47.4,49.975) ; v1(69.15,74.25) 69.15,75.35 69.275,75.475 U5.26@69.275,78.525
  Signal Layer 2 w0.1: v1(48.775,75) 48.897,75 49.047,75.15 51.975,75.15 52.85,74.275 55.2,74.275 55.375,74.45 59.637,74.45 59.837,74.25 v1(69.15,74.25)
  Bottom Layer w0.1: v1(47.4,49.975) 47.4,51.6 48.325,52.525 48.325,65.75 48.85,66.275 48.85,74.925 v1(48.775,75)
ETH1_RX_CLK: R79.1 U14.AA3 | length 67.2
  Top Layer w0.075: 67.35,27.725 67.35,28.3 68.975,29.925 U14.AA3@68.975,30.65
  Top Layer w0.1: v1(48.3,44.275) 48.3,43.75 R79.1@48.425,43.625 ; v1(48.425,21.925) 48.476,21.976 49.178,21.976 49.229,21.925 54.675,21.925 55.25,22.5 55.25,24.125 56.3,25.175 65.576,25.175 65.601,25.15 67,25.15 67.35,25.5 67.35,26.069 67.35,27.725
  Bottom Layer w0.1: v1(48.3,44.275) 48.3,44.175 47.7,43.575 47.7,41.775 47.975,41.5 47.975,30.15 47.925,30.1 47.925,29.825 47.925,29.525 47.825,29.425 47,29.425 46.9,29.325 46.9,29.125 47,29.025 47.825,29.025 47.925,28.925 47.925,28.725 47.825,28.625 47,28.625 46.9,28.525 46.9,28.325 47,28.225 47.825,28.225 47.925,28.125 47.925,27.925 47.825,27.825 47,27.825 46.9,27.725 46.9,27.525 47,27.425 47.825,27.425 47.925,27.325 47.925,27.125 47.825,27.025 47,27.025 46.9,26.925 46.9,26.725 47,26.625 47.825,26.625 47.925,26.525 47.925,26.325 47.825,26.225 47,26.225 46.9,26.125 46.9,25.925 47,25.825 47.825,25.825 47.925,25.725 47.925,25.525 47.825,25.425 47,25.425 46.9,25.325 46.9,25.125 47,25.025 47.825,25.025 47.925,24.925 47.925,24.725 47.825,24.625 47,24.625 46.9,24.525 46.9,24.325 47,24.225 47.825,24.225 47.925,24.125 47.925,23.925 47.825,23.825 47,23.825 46.9,23.725 46.9,23.525 47,23.425 47.825,23.425 47.925,23.325 47.925,23.125 47.825,23.025 47,23.025 46.9,22.925 46.9,22.725 47,22.625 47.825,22.625 47.925,22.525 47.925,22.425 v1(48.425,21.925)
ETH1_RXD0: R98.1 U14.Y7 | length 70
  Top Layer w0.075: 69.9,27.725 69.9,28.263 71.221,29.584 71.221,30.775 70.996,31 70.996,31.129 U14.Y7@70.975,31.15
  Top Layer w0.1: R98.1@52.425,38.2 v1(53.075,38.2) ; v1(56.95,23.95) 57,23.9 64.25,23.9 64.45,23.7 66.425,23.7 67,24.275 68.228,24.275 68.879,24.926 69.162,24.926 69.9,25.664 69.9,27.725
  Bottom Layer w0.1: v1(53.075,38.2) 59.3,38.2 59.65,38.2 59.85,38.2 60,38.35 60,38.525 59.9,38.625 59.85,38.625 59.45,38.625 59.15,38.625 59.05,38.725 59.05,40.75 58.95,40.85 58.75,40.85 58.65,40.75 58.65,38.725 58.55,38.625 58.35,38.625 58.25,38.725 58.25,40.75 58.15,40.85 57.95,40.85 57.85,40.75 57.85,38.725 57.75,38.625 57.55,38.625 57.45,38.725 57.45,40.75 57.35,40.85 57.15,40.85 57.05,40.75 57.05,38.725 56.95,38.625 56.75,38.625 56.65,38.725 56.65,40.75 56.55,40.85 56.35,40.85 56.25,40.75 56.25,38.725 56.15,38.625 56.05,38.625 52.75,38.625 52.4,38.275 52.4,27.025 53.175,26.25 53.175,25.6 53.375,25.4 55.65,25.4 56.824,24.226 56.824,24.197 56.95,24.072 v1(56.95,23.95)
ETH1_RXD1: R109.1 U14.AA7 | length 63.5
  Top Layer w0.075: 69.7,27.725 69.7,28.302 70.975,29.577 70.975,29.816 U14.AA7@70.975,30.65
  Top Layer w0.1: R109.1@52.425,34.975 52.525,35.075 v1(53.1,35.075) ; v1(57.875,24.325) 64.45,24.325 64.875,23.9 66.275,23.9 66.925,24.55 68.22,24.55 68.376,24.706 68.796,25.126 69.079,25.126 69.7,25.747 69.7,27.725
  Bottom Layer w0.1: v1(53.1,35.075) 53.1,37.625 53.283,37.808 53.357,37.808 53.375,37.825 53.591,37.825 53.65,37.766 53.65,37.625 53.725,37.55 57.675,37.55 57.775,37.45 57.775,37.25 57.675,37.15 53.75,37.15 53.65,37.05 53.65,36.85 53.75,36.75 57.675,36.75 57.775,36.65 57.775,36.45 57.675,36.35 53.75,36.35 53.65,36.25 53.65,36.05 53.75,35.95 57.675,35.95 57.775,35.85 57.775,35.65 57.675,35.55 53.75,35.55 53.65,35.45 53.65,35.15 53.65,34.95 52.625,33.925 52.625,27.475 52.96,27.14 54.261,27.14 55.501,25.9 56.325,25.9 57.875,24.35 v1(57.875,24.325)
ETH1_TX_EN: U13.16 U14.AA2 | length 68.2
  Top Layer w0.075: 66.8,27.725 66.8,28.45 68.475,30.125 U14.AA2@68.475,30.65
  Top Layer w0.1: v1(43.075,32.775) 43.075,32.05 43.7,31.425 43.7,31.075 45.5,29.275 53.25,29.275 53.35,29.175 53.675,29.175 53.975,29.175 54.075,29.075 54.075,28.35 54.175,28.25 54.375,28.25 54.475,28.35 54.475,29.075 54.575,29.175 54.775,29.175 54.875,29.075 54.875,28.35 54.975,28.25 55.175,28.25 55.275,28.35 55.275,29.075 55.375,29.175 55.575,29.175 55.675,29.075 55.675,28.35 55.775,28.25 55.975,28.25 56.075,28.35 56.075,29.075 56.175,29.175 56.275,29.175 56.55,28.9 56.55,26.525 57.3,25.775 57.425,25.775 57.575,25.775 57.875,25.775 57.975,25.675 57.975,25.5 58.075,25.4 58.275,25.4 58.375,25.5 58.375,25.675 58.475,25.775 58.675,25.775 58.775,25.675 58.775,25.5 58.875,25.4 59.075,25.4 59.175,25.5 59.175,25.675 59.275,25.775 59.475,25.775 59.575,25.675 59.575,25.5 59.675,25.4 59.875,25.4 59.975,25.5 59.975,25.675 60.075,25.775 60.275,25.775 60.375,25.675 60.375,25.5 60.475,25.4 60.675,25.4 60.775,25.5 60.775,25.675 60.875,25.775 61.075,25.775 61.175,25.675 61.175,25.5 61.275,25.4 61.475,25.4 61.575,25.5 61.575,25.675 61.675,25.775 61.875,25.775 61.975,25.675 61.975,25.5 62.075,25.4 62.275,25.4 62.375,25.5 62.375,25.675 62.475,25.775 62.675,25.775 62.775,25.675 62.775,25.5 62.875,25.4 63.075,25.4 63.175,25.5 63.175,25.675 63.275,25.775 63.475,25.775 63.575,25.675 63.575,25.5 63.675,25.4 63.875,25.4 63.975,25.5 63.975,25.675 64.075,25.775 64.275,25.775 64.375,25.675 64.375,25.5 64.475,25.4 64.675,25.4 64.775,25.5 64.775,25.675 64.875,25.775 65.075,25.775 65.175,25.675 65.175,25.5 65.275,25.4 65.475,25.4 65.575,25.5 65.575,25.675 65.675,25.775 65.775,25.775 65.775,25.8 66.8,26.825 66.8,27.725 ; v1(43.875,44.125) 43.975,44.125 44.075,44.125 44.175,44.225 44.175,47.75 44.275,47.85 44.475,47.85 44.575,47.75 44.575,44.225 44.675,44.125 44.975,44.125 45.375,44.125 45.4,44.125 45.55,44.125 45.7,43.975 45.7,42.475 46.075,42.1 U13.16@46.075,40.975
  Bottom Layer w0.1: v1(43.075,32.775) 43.075,34.525 44.6,36.05 44.6,43.4 v1(43.875,44.125)
ETH1_TXD0: U13.17 U14.AA9 | length 70.5
  Top Layer w0.075: 71.253,27.725 71.975,28.447 U14.AA9@71.975,30.65
  Top Layer w0.087: 71.244,27.725 71.253,27.725
  Top Layer w0.1: v1(40.025,35.875) 40.225,36.075 40.225,41.825 40.925,42.525 44.3,42.525 45.575,41.25 U13.17@45.575,40.975 ; v1(46.475,15.85) 46.9,15.85 51.625,20.575 55.25,20.575 58.175,23.5 66.45,23.5 66.925,23.025 67.725,23.025 67.95,23.25 67.958,23.25 68.575,23.867 68.575,24.057 69.045,24.526 69.328,24.526 70.32,25.518 70.32,26.97 71.075,27.725 71.244,27.725
  Bottom Layer w0.1: v1(40.025,35.875) 40.4,35.875 40.714,35.561 40.714,34.769 42.55,32.933 42.55,32.625 43.35,31.825 43.35,30.97 42.75,30.37 42.75,29.934 43.221,29.462 43.375,29.462 45.45,27.387 45.45,21.319 45.125,20.994 45.125,19.383 46.475,18.033 v1(46.475,15.85)
ETH1_TXD1: U13.18 U14.Y10 | length 72.2
  Top Layer w0.075: 72.092,27.725 72.644,28.277 72.644,30.337 72.721,30.414 72.721,30.779 72.498,31.002 72.498,31.127 U14.Y10@72.475,31.15
  Top Layer w0.1: v1(40.275,35.25) 40.3,35.225 40.5,35.425 40.5,41.7 41.05,42.25 44.05,42.25 45.075,41.225 U13.18@45.075,40.975 ; v1(45.825,15.475) 45.875,15.425 46.95,15.425 51.9,20.375 55.333,20.375 58.258,23.3 66.367,23.3 67.342,22.325 68.725,22.325 69.4,23 69.4,23.75 70.92,25.27 70.92,26.67 71.372,27.122 71.489,27.122 72.092,27.725
  Bottom Layer w0.1: v1(40.275,35.25) 40.275,34.925 42.35,32.85 42.35,32.542 43.15,31.742 43.15,31.053 42.55,30.453 42.55,29.851 43.138,29.262 43.292,29.262 44.527,28.027 44.527,28.024 44.853,27.699 45.25,27.301 45.25,21.402 44.925,21.077 44.925,19.3 45.825,18.4 v1(45.825,15.475)
ETH2_CLK: R50.1 U14.H5 | length 53
  Top Layer w0.09: U14.H5@69.975,37.15 70.1,37.275 v2(70.4,37.275)
  Top Layer w0.1: v1(46.375,49.15) 46.375,50.975 46.375,51.075 46.275,51.175 45.5,51.175 45.4,51.275 45.4,51.475 45.5,51.575 46.375,51.575 47.186,51.575 47.286,51.675 47.286,51.875 47.186,51.975 46.375,51.975 45.5,51.975 45.4,52.075 45.4,52.275 45.5,52.375 46.375,52.375 47.186,52.375 47.286,52.475 47.286,52.675 47.186,52.775 46.375,52.775 45.5,52.775 45.4,52.875 45.4,53.075 45.5,53.175 46.375,53.175 47.186,53.175 47.286,53.275 47.286,53.475 47.186,53.575 46.375,53.575 45.5,53.575 45.4,53.675 45.4,53.875 45.5,53.975 46.375,53.975 47.186,53.975 47.286,54.075 47.286,54.275 47.186,54.375 46.475,54.375 46.375,54.475 46.375,54.775 46.375,54.8 R50.1@46.375,56.85
  Bottom Layer w0.1: v1(46.375,49.15) 46.425,49.1 51.025,49.1 54.075,46.05 55.075,46.05 55.25,46.225 57,46.225 60.525,42.7 60.951,42.7 61.201,42.45 66.975,42.45 68.275,41.15 68.275,38.2 69.2,37.275 v2(70.4,37.275)
ETH2_CRS_DV: R36.1 U14.F4 | length 46.1
  Top Layer w0.09: v2(69.425,38.65) 69.463,38.613 69.463,38.163 U14.F4@69.475,38.15
  Top Layer w0.1: R36.1@52.425,63.65 v1(53.15,63.65) ; v1(61.1,61) 61.05,60.95 61.05,52.825 62.65,51.225 62.65,47.45 63.2,46.9 63.2,45.775 v1(63.125,45.7)
  Bottom Layer w0.1: v1(53.15,63.65) 53.68,63.65 56.228,61.102 56.33,61 56.82,61 56.92,60.9 56.92,60.258 57.02,60.158 57.22,60.158 57.32,60.258 57.32,61.052 57.42,61.152 57.62,61.152 57.72,61.052 57.72,60.258 57.82,60.158 58.02,60.158 58.12,60.258 58.12,61.052 58.22,61.152 58.42,61.152 58.52,61.052 58.52,60.258 58.62,60.158 58.82,60.158 58.92,60.258 58.92,61.052 59.02,61.152 59.22,61.152 59.32,61.052 59.32,60.258 59.42,60.158 59.62,60.158 59.72,60.258 59.72,61.052 59.82,61.152 60.02,61.152 60.12,61.052 60.12,60.258 60.22,60.158 60.42,60.158 60.52,60.258 60.52,60.9 60.62,61 60.895,61 v1(61.1,61) ; v1(63.125,45.7) 64.175,44.65 66.675,44.65 67.6,43.725 67.6,43 68.95,41.65 68.95,39.125 v2(69.425,38.65)
ETH2_MDC: U7.13 U14.G3 | length 47.4
  Top Layer w0.09: U14.G3@68.975,37.65 v2(69.4,37.65)
  Top Layer w0.1: U7.13@47.575,63.35 48.475,63.35 v1(49.1,63.975) ; v1@59.875,64.425 59.875,52.444 61.45,50.869 61.45,43.925 v1(61.775,43.6)
  Signal Layer 2 w0.219: v1(49.1,63.975) 49.425,64.3 v1(59.875,64.3)
  Bottom Layer w0.09: 67.3,43.125 67.3,42.725 68.575,41.45 68.575,38.475 v2(69.4,37.65)
  Bottom Layer w0.1: v1(61.775,43.6) 62.227,44.052 66.829,44.052 67.3,43.581 67.3,43.125
ETH2_MDINT: R30.1 U14.H4 | length 48.8
  Top Layer w0.09: v2(69.4,36.7) 69.4,37.075 U14.H4@69.475,37.15
  Top Layer w0.1: R30.1@48.425,66 v1(48.425,67.2) ; v1(55.4,67.2) 55.525,67.075 55.525,51.35 56.25,50.625 v1(56.25,45.575)
  Signal Layer 2 w0.219: v1(48.425,67.2) 48.45,67.175 55.375,67.175 v1(55.4,67.2)
  Bottom Layer w0.09: 65.175,39.975 66.975,39.975 67.875,39.075 67.875,37.825 69,36.7 v2(69.4,36.7)
  Bottom Layer w0.1: v1(56.25,45.575) 56.25,44.625 60.9,39.975 65.175,39.975
ETH2_MDIO: R31.1 U7.12 U14.J3 | length 48.6
  Top Layer w0.075: 65.175,37.975 66.212,36.938 67.559,36.938 67.601,36.897 68.728,36.897 U14.J3@68.975,36.65
  Top Layer w0.1: U7.12@48.275,62.65 48.975,62.65 49.725,63.4 49.725,65.075 v1(50.45,65.8) R31.1@51.525,65.8 ; v1(55.05,65.8) 55.275,65.575 55.275,44.325 60.65,38.95 64.2,38.95 65.175,37.975
  Signal Layer 2 w0.219: v1(50.45,65.8) v1(55.05,65.8)
ETH2_NRST: R25.1 R26.1 R28.1 U5.27 | length 38.7
  Top Layer w0.1: v1(45.725,68.025) R25.1@46.35,68.025 R26.1@46.35,66.95 46.35,66.075 R28.1@46.275,66 ; U5.27@69.925,78.525 69.925,77.3 v1(70.175,77.05)
  Signal Layer 2 w0.1: v1(45.925,77.425) 46.225,77.725 49.5,77.725 49.725,77.5 61.1,77.5 61.425,77.825 65.5,77.825 66.275,77.05 v1(70.175,77.05)
  Bottom Layer w0.1: v1(45.725,68.025) 45.725,73.9 45.925,74.1 v1(45.925,77.425)
ETH2_RXD0: R41.1 U14.N2 | length 43.6
  Top Layer w0.075: 65.175,33.55 65.625,33.55 66.479,34.404 68.077,34.404 68.323,34.65 U14.N2@68.475,34.65
  Top Layer w0.1: v1(52,55.575) 51.7,55.275 51.7,45.2 54.725,42.175 v2(54.725,33.975) ; R41.1@52.425,60.575 52.45,60.55 v1(53.05,60.55) ; v2(64.375,33.55) 65.175,33.55
  Bottom Layer w0.1: v1(52,55.575) 52,59.5 v1(53.05,60.55) ; v2(54.725,33.975) 57.075,33.975 57.325,34.225 63.05,34.225 63.725,33.55 v2(64.375,33.55)
ETH2_RXD1: R51.1 U14.N1 | length 46.5
  Top Layer w0.075: v2(64.925,33.9) 65.175,33.9 65.65,33.9 66.4,34.65 U14.N1@67.975,34.65
  Top Layer w0.1: R51.1@52.425,57.35 52.6,57.175 52.6,55.325 51.95,54.675 51.95,45.3 52.205,45.045 55.225,42.024 55.225,38.75 55.225,38.65 55.325,38.55 55.975,38.55 56.075,38.45 56.075,38.25 55.975,38.15 55.225,38.15 55.175,38.15 55.075,38.05 55.075,37.85 55.175,37.75 55.225,37.75 55.975,37.75 56.075,37.65 56.075,37.45 55.975,37.35 55.225,37.35 55.175,37.35 55.075,37.25 55.075,37.05 55.175,36.95 55.225,36.95 55.975,36.95 56.075,36.85 56.075,36.65 55.975,36.55 55.225,36.55 55.175,36.55 55.075,36.45 55.075,36.25 55.175,36.15 55.225,36.15 55.975,36.15 56.075,36.05 56.075,35.85 55.975,35.75 55.225,35.75 55.175,35.75 55.075,35.65 55.075,35.45 55.175,35.35 55.225,35.35 55.975,35.35 56.075,35.25 56.075,35.05 55.975,34.95 55.325,34.95 55.225,34.85 55.225,34.55 55.25,34.525 55.253,34.522 v2(55.253,34.402)
  Bottom Layer w0.1: v2(55.253,34.402) 55.301,34.45 64.375,34.45 v2(64.925,33.9)
ETH2_TX_EN: U7.16 U14.G1 | length 58.9
  Top Layer w0.075: 65.175,39.2 66.725,37.65 U14.G1@67.975,37.65
  Top Layer w0.1: v1(45.45,64.85) 45.55,64.85 46.075,64.325 U7.16@46.075,63.35 ; v1(58.45,64.85) 58.45,60.975 58.45,60.85 58.45,60.55 58.35,60.45 57.125,60.45 57.025,60.35 57.025,60.15 57.125,60.05 58.35,60.05 58.45,59.95 58.45,59.75 58.35,59.65 57.125,59.65 57.025,59.55 57.025,59.35 57.125,59.25 58.35,59.25 58.45,59.15 58.45,58.95 58.35,58.85 57.125,58.85 57.025,58.75 57.025,58.55 57.125,58.45 58.35,58.45 58.45,58.35 58.45,58.15 58.35,58.05 57.125,58.05 57.025,57.95 57.025,57.75 57.125,57.65 58.35,57.65 58.45,57.55 58.45,57.45 58.45,50.675 60.375,48.75 60.375,41.05 61.375,40.05 64.325,40.05 65.175,39.2
  Signal Layer 2 w0.219: v1(45.45,64.85) v1(58.45,64.85)
ETH2_TXD0: U7.17 U14.P3 | length 58
  Top Layer w0.075: 65.175,32.7 65.575,32.7 66.772,33.897 68.572,33.897 68.825,34.15 U14.P3@68.975,34.15
  Top Layer w0.1: U7.17@45.575,63.35 v1(45.575,64.125) ; v1(51.653,32.952) 51.627,32.952 51.625,32.95 51.875,32.7 55.566,32.7 55.616,32.75 58.434,32.75 58.484,32.7 65.175,32.7
  Bottom Layer w0.1: v1(45.575,64.125) 46.65,64.125 47.9,62.875 47.9,52.95 45.4,50.45 45.4,48.4 45.575,48.225 50.2,48.225 51.625,46.8 51.625,44.401 51.6,44.376 51.6,34 51.653,33.947 v1(51.653,32.952)
ETH2_TXD1: U7.18 U14.R2 | length 57.2
  Top Layer w0.075: v2@66.898,33.225 66.905,33.225 67.161,33.481 67.644,33.481 67.725,33.4 68.225,33.4 U14.R2@68.475,33.65
  Top Layer w0.09: v2(66.875,33.225) v2@66.898,33.225
  Top Layer w0.1: v1(44.7,64.525) 45.075,64.15 U7.18@45.075,63.35 ; v1(50.6,34.025) 53.65,34.025 53.669,34.006 v1(53.669,33.9)
  Bottom Layer w0.1: v1(44.7,64.525) 44.701,64.524 44.701,63.974 45.366,63.309 46.266,63.309 46.85,62.725 46.85,52.35 45.1,50.6 45.1,48.275 45.55,47.825 49.4,47.825 50.125,47.1 50.125,46.95 50.6,46.475 v1(50.6,34.025) ; v1(53.669,33.9) 54.419,33.15 57.149,33.15 57.199,33.1 57.551,33.1 57.601,33.15 60.449,33.15 60.474,33.125 60.826,33.125 60.851,33.15 62.824,33.15 62.849,33.125 63.201,33.125 63.226,33.15 66.8,33.15 v2(66.875,33.225)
